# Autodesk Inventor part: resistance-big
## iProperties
Author: chr
Created: 2001-06
Part Number: resistance-big
Material: Par défaut
Document SubType Name: Modélisation
Designer: chr
Control State: 0
Master: False
Checked Out: False
PropertySet Name: Design Tracking Control
Shininess: 41.0
PropertySet Name: _Private Model Information
Length Units: 11269
Angle Units: 11286
Time Units: 11279
Mass Units: 11290
Length Display Precision: 3
Angle Display Precision: 2
Compacted: False
Density: 0.0
Volumn: 0.0
Area: 0.0
PropertySet Name: Model Information
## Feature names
1. Extrusion1
2. Balayage1
3. Symétrie1 [Mirror]
